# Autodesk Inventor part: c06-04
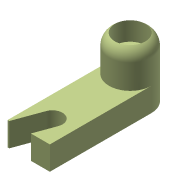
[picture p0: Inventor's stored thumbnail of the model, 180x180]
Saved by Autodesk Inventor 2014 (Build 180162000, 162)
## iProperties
Created: 2013-03
Part Number: c06-04
Material: Aluminum 6061
Document SubType Name: Modeling
Designer: Thom Tremblay
Density: 2.71 g/cm^3
Appearance: Zinc Chromate 2
Author: Thom Tremblay
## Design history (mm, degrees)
sketch "Sketch1"
  geometry: L1 (0, -12.5)-(60, -12.5); L2 (60, -12.5)-(60, 12.5); L3 (60, 12.5)-(0, 12.5); L4 (0, 12.5)-(0, -12.5); 2 further points
  constraints: 8 end point, 2 parallel, 1 coincident, 1 horizontal, 1 midpoint, 1 perpendicular
  dimensions: "d1" = 25 distance of L2.end L1.end; "d2" = 60 distance of L2.end L3.end
extrude "Base" new body sketch "Sketch1" distance "d3" = 14; taper "d4" = 0 deg
sketch "Sketch2"
  geometry: C1 r 12.5 at (0, 0); 1 further point
  constraints: 1 centre point, 1 coincident
extrude "Boss" join sketch "Sketch2" distance "d5" = 35; taper "d6" = 0 deg
sketch "Sketch3"
  geometry: L1 (-60, 12.5)-(-60, -12.5) reference; L2 (-60, -6)-(-60, 6); L3 (-43.948, 5.638)-(-60, 11.481); L4 (-48.052, -5.638)-(-60, -1.289); L5 (-60, 11.481)-(-60, -1.289); A1 r 6 centre (-46, 0) between (-43.948, 5.638) and (-48.052, -5.638); 2 further points
  constraints: 8 end point, 3 midpoint, 2 point on circle, 2 point on line, 2 tangent, 1 centre point, 1 collinear, 1 horizontal alignment, 1 parallel
  dimensions: "d8" = 12 diameter of A1; "d20" = 20 dimension on A1 L1; "d27" = 70 deg angle of L1 L3
extrude "Slot" cut sketch "Sketch3" stored distance "d9" = 24; taper "d10" = 0 deg
hole "Hole1" diameter "d13" = 11; stored, may be unused: countersink angle "d17" = 90 deg, drill point angle "d19" = 118 deg; dims "d11" = 10, "d12" = 10, "d14" = 6, "d15" = 18, "d16" = 11, "d18" = 8
fillet "Fillet1" dims "d26" = 8
node "Midplane between faces"
body "Solid1"
